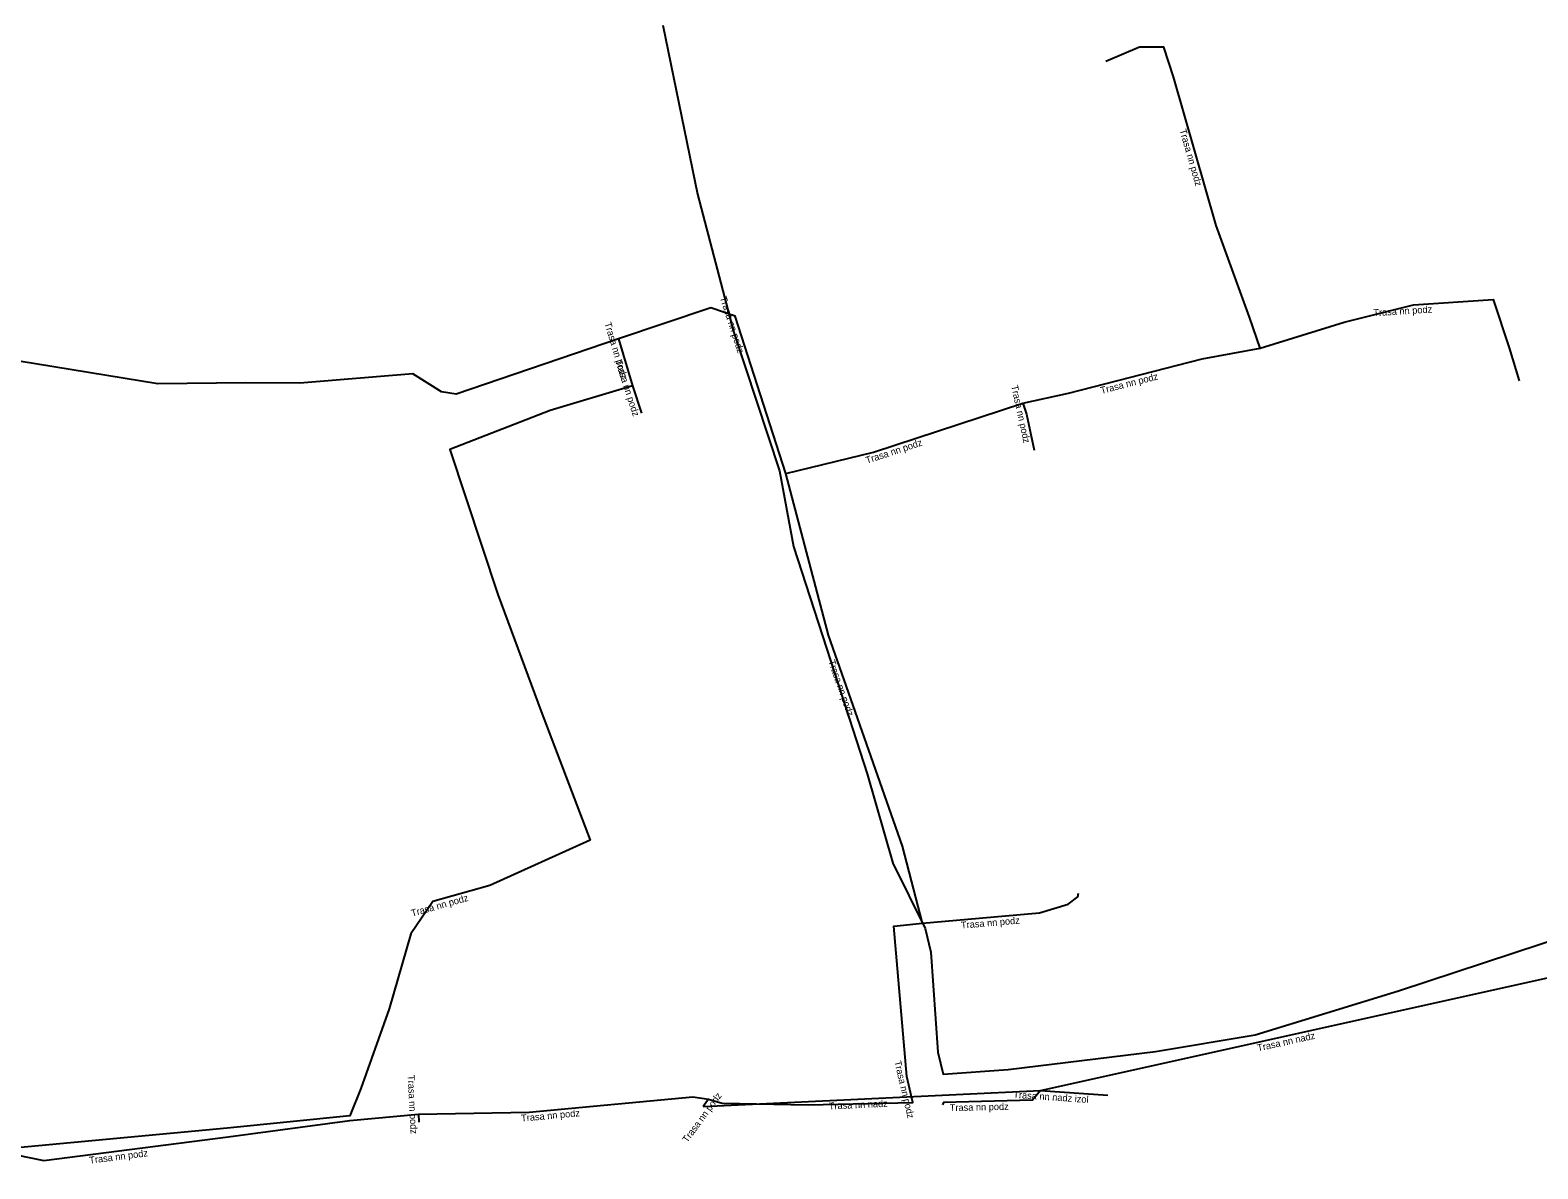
# Model space of a CAD drawing. Extents: x -682605 to -681812, y -1059958 to -1059650.
# Drawn here: x -682490.6 to -682381.3, y -1059850.4 to -1059767.8 of the extents above; entities that cross this region are included whole.
import ezdxf

# ---------------------------------------------------------------- set-up
doc = ezdxf.new("R2010")
doc.units = 0
for name, color, linetype in [('Popiskový text - Ostatní atributy Trasy', 7, 'Continuous'), ('Spojnice NN', 7, 'Continuous'), ('Spojnice VN', 7, 'Continuous')]:
    doc.layers.add(name, color=color, linetype=linetype)

msp = doc.modelspace()

# ---------------------------------------------------------------- linework, layer by layer
at = {"layer": 'Spojnice NN'}
for points in [[(-682447.96, -1059790.21), (-682459.73, -1059794.22), (-682460.78, -1059794.04), (-682462.86, -1059792.75), (-682471.05, -1059793.41), (-682474.96, -1059793.4), (-682481.35, -1059793.46), (-682493.93, -1059791.42), (-682506.56, -1059788.09), (-682521.99, -1059781.45), (-682525.52, -1059778.64), (-682528.18, -1059775.05), (-682529.63, -1059771.35), (-682532.33, -1059768.34), (-682552.54, -1059758.22), (-682567.03, -1059749.33), (-682579.9, -1059742.47), (-682589.71, -1059735.91), (-682599.88, -1059730.78)], [(-682401.45, -1059790.87), (-682402.21, -1059788.64), (-682404.64, -1059781.98), (-682407.73, -1059771.22), (-682408.44, -1059769.05), (-682410.2, -1059769.05), (-682412.64, -1059770.1)], [(-682401.45, -1059790.87), (-682395.35, -1059788.99), (-682390.33, -1059787.73), (-682384.55, -1059787.36), (-682383.4, -1059790.85), (-682382.67, -1059793.24)], [(-682435.82, -1059799.97), (-682439.5, -1059788.57), (-682441.27, -1059787.95), (-682447.96, -1059790.21)], [(-682447.96, -1059790.21), (-682446.94, -1059793.6)], [(-682418.65, -1059794.86), (-682415.35, -1059794.14), (-682405.66, -1059791.66), (-682401.45, -1059790.87)], [(-682446.94, -1059793.6), (-682452.91, -1059795.41), (-682460.18, -1059798.23), (-682456.71, -1059808.73), (-682453.56, -1059817.22), (-682450.01, -1059826.56), (-682457.29, -1059829.84), (-682461.41, -1059831), (-682463.01, -1059833.35), (-682464.59, -1059838.79), (-682466.62, -1059844.55), (-682467.42, -1059846.53), (-682476.33, -1059847.43), (-682491.53, -1059848.85), (-682499.99, -1059849.65), (-682504.05, -1059850.38)], [(-682446.94, -1059793.6), (-682446.29, -1059795.6)], [(-682435.82, -1059799.97), (-682429.48, -1059798.42), (-682418.65, -1059794.86)], [(-682418.65, -1059794.86), (-682418.39, -1059795.66), (-682417.82, -1059798.28)], [(-682425.93, -1059832.56), (-682427.37, -1059826.99), (-682432.74, -1059811.69), (-682435.82, -1059799.97)], [(-682425.93, -1059832.56), (-682417.45, -1059831.82), (-682415.36, -1059831.18), (-682414.66, -1059830.67), (-682414.62, -1059830.39)], [(-682441.43, -1059845.33), (-682440.43, -1059845.62), (-682434.2, -1059845.75), (-682426.61, -1059845.56), (-682427.05, -1059843.69), (-682428.01, -1059832.79), (-682425.93, -1059832.56)], [(-682417.36, -1059844.71), (-682379.97, -1059836.39)], [(-682462.45, -1059846.41), (-682454.44, -1059846.26), (-682442.57, -1059845.16), (-682441.43, -1059845.33)], [(-682441.82, -1059845.86), (-682417.36, -1059844.71)], [(-682441.43, -1059845.33), (-682441.82, -1059845.86)], [(-682417.36, -1059844.71), (-682417.96, -1059845.41), (-682424.39, -1059845.56), (-682424.46, -1059845.74)], [(-682417.36, -1059844.71), (-682412.5, -1059845.04)], [(-682504.05, -1059850.38), (-682499.91, -1059850.09), (-682491.62, -1059849.36), (-682489.62, -1059849.78), (-682476.24, -1059848.06), (-682467.43, -1059846.87), (-682462.45, -1059846.41)], [(-682462.45, -1059846.41), (-682462.42, -1059847)]]:
    msp.add_lwpolyline(points, dxfattribs=at)
at = {"layer": 'Spojnice VN'}
for points in [[(-682444.75, -1059767.47), (-682442.22, -1059779.72), (-682439.62, -1059789.68), (-682436.28, -1059799.78), (-682435.27, -1059805.25), (-682432.27, -1059814.5), (-682429.93, -1059821.74), (-682428.06, -1059828.23), (-682425.74, -1059832.96), (-682425.31, -1059834.68), (-682424.81, -1059841.93), (-682424.42, -1059843.52), (-682419.71, -1059843.18)], [(-682419.71, -1059843.18), (-682409.04, -1059841.86), (-682401.8, -1059840.66), (-682391.43, -1059837.47), (-682378.96, -1059833.37), (-682366.87, -1059827.88), (-682350.77, -1059821.14), (-682334.98, -1059814.51), (-682322.31, -1059809.45), (-682316.78, -1059807.47), (-682307.06, -1059804.21), (-682298.09, -1059802), (-682285.23, -1059800.25), (-682273.9, -1059799.1), (-682259.98, -1059797.91), (-682246.72, -1059796.96), (-682230, -1059795.42), (-682225.98, -1059795.71), (-682224.89, -1059801.14), (-682222.94, -1059818.12), (-682221.47, -1059834.28)]]:
    msp.add_lwpolyline(points, dxfattribs=at)

# ---------------------------------------------------------------- texts
at = {"layer": 'Popiskový text - Ostatní atributy Trasy'}
for s, rotation, p in [('Trasa nn podz', 286.0227, (-682407.3, -1059775.07)), ('Trasa nn podz', 287.8904, (-682440.62, -1059787.22)), ('Trasa nn podz', 3.6627, (-682393.23, -1059788.57)), ('Trasa nn podz', 286.7458, (-682448.98, -1059789.08)), ('Trasa nn podz', 288.0042, (-682448.21, -1059791.81)), ('Trasa nn podz', 14.3558, (-682412.95, -1059794.2)), ('Trasa nn podz', 282.2739, (-682419.5, -1059793.62)), ('Trasa nn podz', 18.1965, (-682429.95, -1059799.26)), ('Trasa nn podz', 289.3401, (-682432.76, -1059813.58)), ('Trasa nn podz', 15.7247, (-682462.91, -1059832.1)), ('Trasa nn podz', 4.9872, (-682423.11, -1059832.97)), ('Trasa nn nadz', 12.545, (-682401.6, -1059841.87)), ('Trasa nn podz', 283.2405, (-682427.97, -1059842.6)), ('Trasa nn podz', 272.9108, (-682463.24, -1059843.59)), ('Trasa nn podz', 53.6525, (-682442.97, -1059848.52)), ('Trasa nn nadz', 2.6918, (-682432.7, -1059846.08)), ('Trasa nn nadz izol', 356.0835, (-682419.35, -1059845.23)), ('Trasa nn podz', 5.2945, (-682454.99, -1059846.96)), ('Trasa nn podz', 1.3364, (-682423.94, -1059846.2)), ('Trasa nn podz', 7.3252, (-682486.28, -1059850.01))]:
    msp.add_text(s, height=0.5, rotation=rotation, dxfattribs=at).set_placement(p)

doc.saveas('drawing.dxf')
